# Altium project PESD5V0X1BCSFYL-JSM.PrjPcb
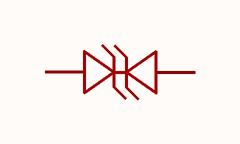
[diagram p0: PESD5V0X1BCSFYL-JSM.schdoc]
1 sheet, 1 parts. Net scope: global (net labels, ports and power ports of the same name join across sheets).

## Sheet PESD5V0X1BCSFYL-JSM.schdoc
size 127 x 101 mm

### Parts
D?  pesd5v0x1bcsfyl-jsm  [DFN0603-2L-BI]  (value not drawn)

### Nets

Not connected (* = marked no-connect by the designer): D? 1 2

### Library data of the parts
D? = pesd5v0x1bcsfyl-jsm: 极性:双向;反向截止电压(Vrwm):5V;钳位电压:5.5V;峰值脉冲电流(Ipp):6.5A@8/20us;峰值脉冲功率(Ppp):50W@8/20us;击穿电压(VBR):8.1V;; Manufacturer: JSMSEMI(杰盛微); AddInBom: yes; ModelId: 27373427bde74123a6c29df2d43fb649; ModelName: DFN0603-2L-BI-L0.6-W0.3-H0.3; ModelTransform: 23.622,11.811,0,0,0,0,0,0,0; Polarity: 双向; Reverse Stand-Off Voltage (Vrwm): 5V; Clamping Voltage: 5.5V; Voltage - Breakdown: 8.1V; Reverse Leakage Current (Ir): 1nA; Number of Channels: 单路; level of protection: IEC 61000-4-5；IEC 61000-4-2; Type: ESD; Junction Capacitance: 0.14pF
